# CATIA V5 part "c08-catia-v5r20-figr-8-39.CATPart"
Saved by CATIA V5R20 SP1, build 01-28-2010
Part number: Part2
Bounding box of the stored display mesh (mm): x -50 to 50, y -50 to 50, z 0 to 40
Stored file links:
  D:\v5_r20\psrt_files_downloaded\c08-catia-v5r20-prt\c08-catia-v5r20-figr-8-39.CATPart
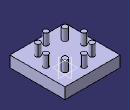
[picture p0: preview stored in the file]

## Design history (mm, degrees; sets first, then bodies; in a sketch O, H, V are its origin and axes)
Body1 (main body)
  Sketch1 on xy-plane, origin (0, 0, 0), H (1, 0, 0), V (0, 1, 0)
    line L1 (-50, 50) -> (50, 50)
    line L2 (50, 50) -> (50, -50)
    line L3 (50, -50) -> (-50, -50)
    line L4 (-50, -50) -> (-50, 50)
    axis line L5 (50, -50) -> (-50, 50)
    length L2 = 100
    length L3 = 100
    horizontal: L1 H, L3 H
    vertical: L2 V, L4 V
    midpoint: O L5
  Pad1: profile Sketch1, direction (0, 0, 1), length 20
  Sketch2 on face of Pad1, origin (0, 0, 20), H (1, 0, 0), V (0, 1, 0)
    circle A1 centre (0, -34.6458) radius 4.7511
    point P1 (0, -34.6458)
    coincidence: P1 V
  Pad2: profile Sketch2, direction (0, 0, 1), length 20
  CircPattern1: of Pad2, instances 8, angular step 45, axis from edge of Sketch3
  Sketch3 on yz-plane, origin (0, 0, 0), H (0, 1, 0), V (0, 0, 1)
    line L1 (0, 0) -> (0, 20.0386)
    vertical: L1 V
